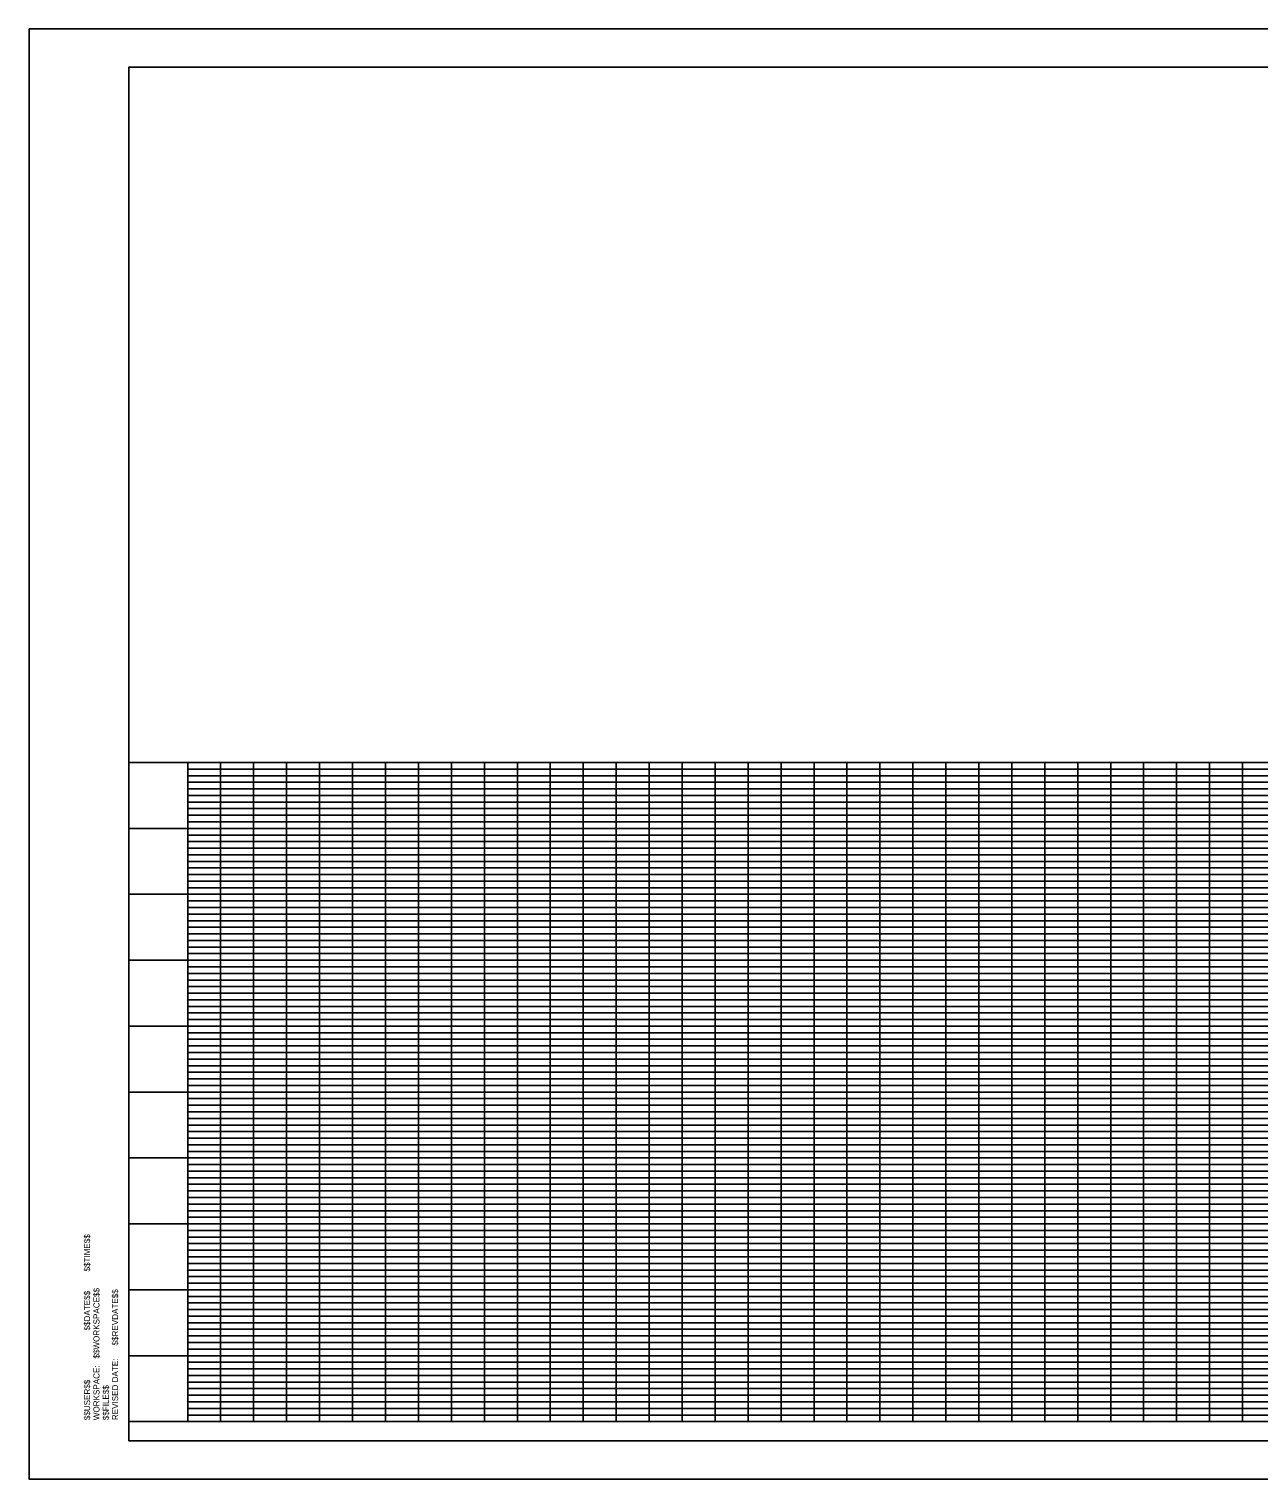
# Model space of a CAD drawing. Extents: x 0 to 1228740, y 0 to 152440.
# Drawn here: x 0 to 18.66, y 0 to 22 of the extents above; entities that cross this region are included whole.
import ezdxf

# ---------------------------------------------------------------- set-up
doc = ezdxf.new("R2010")
doc.units = 0
for name, color, linetype in [('G-TBLK', 7, 'Continuous'), ('R_Border', 7, 'Continuous'), ('R_Grid', 7, 'Continuous'), ('R_No Plot', 7, 'Continuous')]:
    doc.layers.add(name, color=color, linetype=linetype)

msp = doc.modelspace()

# ---------------------------------------------------------------- linework, layer by layer
at = {"layer": 'R_Border'}
for p, q in [((1.516, 21.423), (33.423, 21.423)), ((1.516, 0.577), (1.516, 21.423)), ((33.423, 0.577), (1.516, 0.577))]:
    msp.add_line(p, q, dxfattribs=at)
msp.add_lwpolyline([(34, 22), (0, 22), (0, 0), (34, 0)], close=True, dxfattribs=at)
at = {"layer": 'R_Grid'}
for p, q in [((33.423, 10.871), (1.516, 10.871)), ((2.407, 0.871), (2.407, 10.871)), ((2.907, 0.871), (2.907, 10.871)), ((3.407, 0.871), (3.407, 10.871)), ((3.907, 0.871), (3.907, 10.871)), ((4.407, 0.871), (4.407, 10.871)), ((4.907, 0.871), (4.907, 10.871)), ((5.407, 0.871), (5.407, 10.871)), ((5.907, 0.871), (5.907, 10.871)), ((6.407, 0.871), (6.407, 10.871)), ((6.907, 0.871), (6.907, 10.871)), ((7.407, 0.871), (7.407, 10.871)), ((7.907, 0.871), (7.907, 10.871)), ((8.407, 0.871), (8.407, 10.871)), ((8.907, 0.871), (8.907, 10.871)), ((9.407, 0.871), (9.407, 10.871)), ((9.907, 0.871), (9.907, 10.871)), ((10.407, 0.871), (10.407, 10.871)), ((10.907, 0.871), (10.907, 10.871)), ((11.407, 0.871), (11.407, 10.871)), ((11.907, 0.871), (11.907, 10.871)), ((12.407, 0.871), (12.407, 10.871)), ((12.907, 0.871), (12.907, 10.871)), ((13.407, 0.871), (13.407, 10.871)), ((13.907, 0.871), (13.907, 10.871)), ((14.407, 0.871), (14.407, 10.871)), ((14.907, 0.871), (14.907, 10.871)), ((15.407, 0.871), (15.407, 10.871)), ((15.907, 0.871), (15.907, 10.871)), ((16.407, 0.871), (16.407, 10.871)), ((16.907, 0.871), (16.907, 10.871)), ((17.407, 0.871), (17.407, 10.871)), ((17.907, 0.871), (17.907, 10.871)), ((18.407, 0.871), (18.407, 10.871)), ((32.407, 10.771), (2.407, 10.771)), ((32.407, 10.671), (2.407, 10.671)), ((32.407, 10.571), (2.407, 10.571)), ((32.407, 10.471), (2.407, 10.471)), ((32.407, 10.371), (2.407, 10.371)), ((32.407, 10.271), (2.407, 10.271)), ((32.407, 10.171), (2.407, 10.171)), ((32.407, 10.071), (2.407, 10.071)), ((32.407, 9.971), (2.407, 9.971)), ((33.423, 9.871), (1.516, 9.871)), ((32.407, 9.771), (2.407, 9.771)), ((32.407, 9.671), (2.407, 9.671)), ((32.407, 9.571), (2.407, 9.571)), ((32.407, 9.471), (2.407, 9.471)), ((32.407, 9.371), (2.407, 9.371)), ((32.407, 9.271), (2.407, 9.271)), ((32.407, 9.171), (2.407, 9.171)), ((32.407, 9.071), (2.407, 9.071)), ((33.423, 8.871), (1.516, 8.871)), ((32.407, 8.971), (2.407, 8.971)), ((32.407, 8.771), (2.407, 8.771)), ((32.407, 8.671), (2.407, 8.671)), ((32.407, 8.571), (2.407, 8.571)), ((32.407, 8.471), (2.407, 8.471)), ((32.407, 8.371), (2.407, 8.371)), ((32.407, 8.271), (2.407, 8.271)), ((32.407, 8.171), (2.407, 8.171)), ((32.407, 8.071), (2.407, 8.071)), ((32.407, 7.971), (2.407, 7.971)), ((33.423, 7.871), (1.516, 7.871)), ((32.407, 7.771), (2.407, 7.771)), ((32.407, 7.671), (2.407, 7.671)), ((32.407, 7.571), (2.407, 7.571)), ((32.407, 7.471), (2.407, 7.471)), ((32.407, 7.371), (2.407, 7.371)), ((32.407, 7.271), (2.407, 7.271)), ((32.407, 7.171), (2.407, 7.171)), ((32.407, 7.071), (2.407, 7.071)), ((33.423, 6.871), (1.516, 6.871)), ((32.407, 6.971), (2.407, 6.971)), ((32.407, 6.771), (2.407, 6.771)), ((32.407, 6.671), (2.407, 6.671)), ((32.407, 6.571), (2.407, 6.571)), ((32.407, 6.471), (2.407, 6.471)), ((32.407, 6.371), (2.407, 6.371)), ((32.407, 6.271), (2.407, 6.271)), ((32.407, 6.171), (2.407, 6.171)), ((32.407, 6.071), (2.407, 6.071)), ((32.407, 5.971), (2.407, 5.971)), ((33.423, 5.871), (1.516, 5.871)), ((32.407, 5.771), (2.407, 5.771)), ((32.407, 5.671), (2.407, 5.671)), ((32.407, 5.571), (2.407, 5.571)), ((32.407, 5.471), (2.407, 5.471)), ((32.407, 5.371), (2.407, 5.371)), ((32.407, 5.271), (2.407, 5.271)), ((32.407, 5.171), (2.407, 5.171)), ((32.407, 5.071), (2.407, 5.071)), ((33.423, 4.871), (1.516, 4.871)), ((32.407, 4.971), (2.407, 4.971)), ((32.407, 4.771), (2.407, 4.771)), ((32.407, 4.671), (2.407, 4.671)), ((32.407, 4.571), (2.407, 4.571)), ((32.407, 4.471), (2.407, 4.471)), ((32.407, 4.371), (2.407, 4.371)), ((32.407, 4.271), (2.407, 4.271)), ((32.407, 4.171), (2.407, 4.171)), ((32.407, 4.071), (2.407, 4.071)), ((32.407, 3.971), (2.407, 3.971)), ((33.423, 3.871), (1.516, 3.871)), ((32.407, 3.771), (2.407, 3.771)), ((32.407, 3.671), (2.407, 3.671)), ((32.407, 3.571), (2.407, 3.571)), ((32.407, 3.471), (2.407, 3.471)), ((32.407, 3.371), (2.407, 3.371)), ((32.407, 3.271), (2.407, 3.271)), ((32.407, 3.171), (2.407, 3.171)), ((33.423, 2.871), (1.516, 2.871)), ((32.407, 3.071), (2.407, 3.071)), ((32.407, 2.971), (2.407, 2.971)), ((32.407, 2.771), (2.407, 2.771)), ((32.407, 2.671), (2.407, 2.671)), ((32.407, 2.571), (2.407, 2.571)), ((32.407, 2.471), (2.407, 2.471)), ((32.407, 2.371), (2.407, 2.371)), ((32.407, 2.271), (2.407, 2.271)), ((32.407, 2.171), (2.407, 2.171)), ((32.407, 2.071), (2.407, 2.071)), ((33.423, 1.871), (1.516, 1.871)), ((32.407, 1.971), (2.407, 1.971)), ((32.407, 1.771), (2.407, 1.771)), ((32.407, 1.671), (2.407, 1.671)), ((32.407, 1.571), (2.407, 1.571)), ((32.407, 1.471), (2.407, 1.471)), ((32.407, 1.371), (2.407, 1.371)), ((32.407, 1.271), (2.407, 1.271)), ((32.407, 1.171), (2.407, 1.171)), ((32.407, 1.071), (2.407, 1.071)), ((32.407, 0.971), (2.407, 0.971)), ((33.423, 0.871), (1.516, 0.871))]:
    msp.add_line(p, q, dxfattribs=at)
at = {"layer": 'R_No Plot'}
for points in [[(33.423, 17.405), (33.423, 10.871), (1.516, 10.871), (1.516, 21.423), (25.197, 21.423), (25.197, 20.435), (28.749, 20.435), (28.749, 20.078), (29.113, 20.078), (29.113, 20.143), (30.667, 20.143)], [(33.423, 17.405), (33.423, 0.577), (1.516, 0.577), (1.516, 21.423), (25.197, 21.423), (25.197, 20.435), (28.749, 20.435), (28.749, 20.078), (29.113, 20.078), (29.113, 20.143), (30.667, 20.143)]]:
    msp.add_lwpolyline(points, dxfattribs=at)
for points in [[(1.516, 21.423), (33.423, 21.423), (33.423, 0.577), (1.516, 0.577)], [(1.516, 10.871), (33.423, 10.871), (33.423, 0.577), (1.516, 0.577)]]:
    msp.add_lwpolyline(points, close=True, dxfattribs=at)

# ---------------------------------------------------------------- texts
at = {"layer": 'G-TBLK'}
for s, p in [('$$TIME$$', (0.927, 3.148)), ('$$WORKSPACE$$', (1.069, 1.827)), ('$$REVDATE$$', (1.352, 2.026)), ('$$DATE$$', (0.927, 2.254)), ('REVISED DATE:', (1.352, 0.893)), ('WORKSPACE:', (1.069, 0.892)), ('$$USER$$', (0.927, 0.892)), ('$$FILE$$', (1.211, 0.892))]:
    msp.add_text(s, height=0.0918, rotation=90, dxfattribs=at).set_placement(p)

doc.saveas('drawing.dxf')
